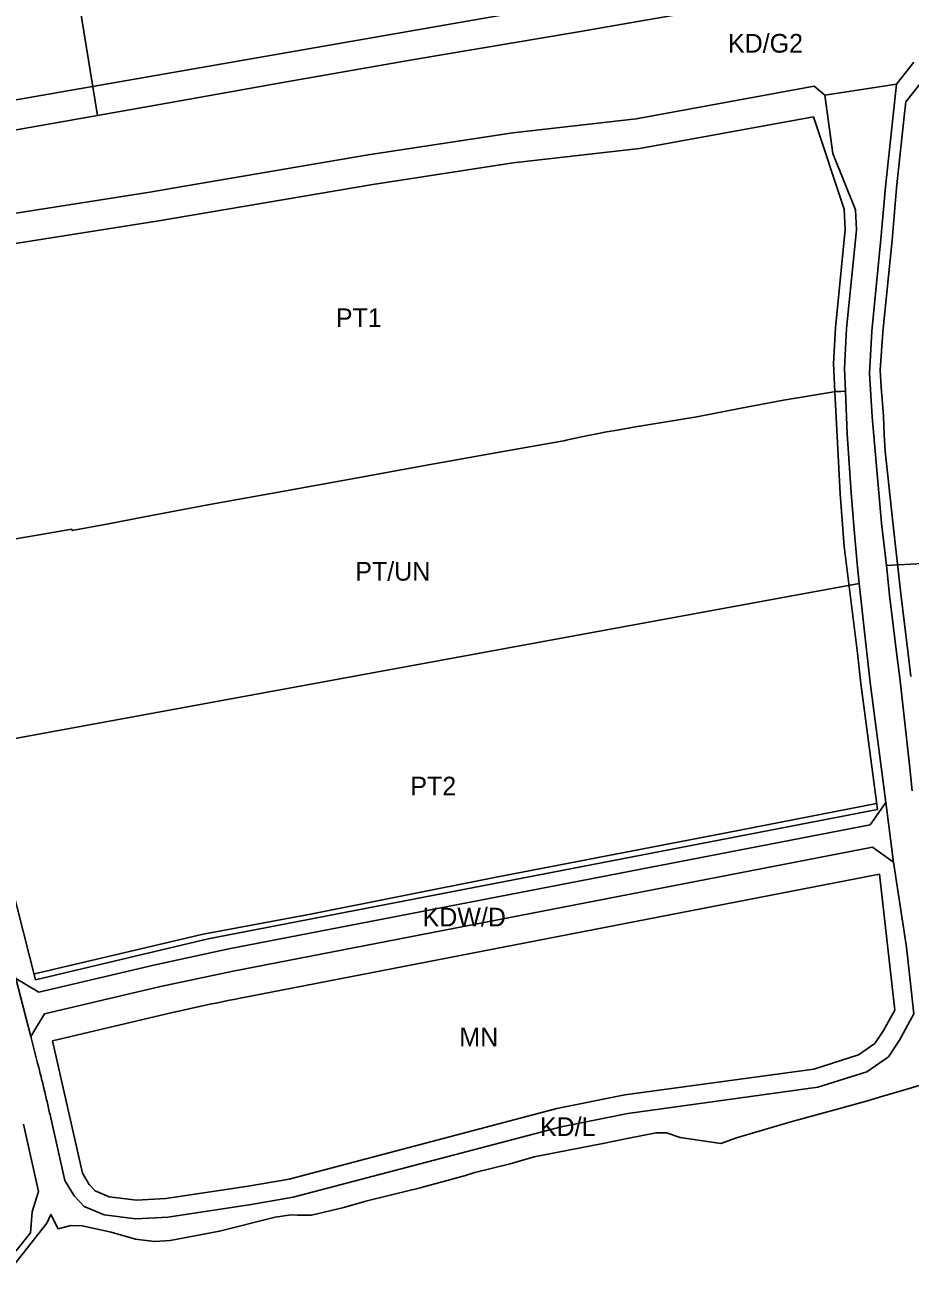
# Model space of a CAD drawing. Extents: x 7436680 to 7439366, y 5548361 to 5550775.
# Drawn here: x 7437960 to 7438434, y 5548459 to 5549127 of the extents above; entities that cross this region are included whole.
import ezdxf

# ---------------------------------------------------------------- set-up
doc = ezdxf.new("R2010")
doc.units = 0
for name, color, linetype in [('linie_rozgraniczajace', 7, 'Continuous'), ('linie_zabudowy_azurowe', 7, 'Continuous'), ('linie_zabudowy_nieprzekraczalne', 7, 'Continuous'), ('oznaczenia_przeznaczen', 7, 'Continuous')]:
    doc.layers.add(name, color=color, linetype=linetype)

msp = doc.modelspace()

# ---------------------------------------------------------------- linework, layer by layer
at = {"layer": 'linie_rozgraniczajace'}
for points in [[(7437970.79, 5549253.27), (7438227.34, 5549301.19), (7438338.8, 5549322.13), (7438378.49, 5549334.48), (7438391.14, 5549280.09), (7438396.35, 5549239.37), (7438392.82, 5549198.47), (7438390.24, 5549185.26), (7438355.6, 5549161.53), (7438356.27, 5549140.95), (7438335.28, 5549136.91), (7438255.31, 5549123.14), (7438167.47, 5549108.23), (7438100.24, 5549096.55), (7438038.34, 5549085.45), (7437999.18, 5549078.49), (7437982.05, 5549183.92)], [(7437920.81, 5548738.78), (7438406.56, 5548827.93), (7438408.3, 5548811.89), (7438409.18, 5548803.76), (7438412.31, 5548775.06), (7438420.83, 5548710.69), (7438412.33, 5548698.87), (7438069.39, 5548632.36), (7438029.98, 5548623.9), (7437967.7, 5548609.21), (7437955.49, 5548616.6), (7437930.18, 5548715.57)], [(7437955.49, 5548616.6), (7437967.7, 5548609.21), (7438029.98, 5548623.9), (7438069.39, 5548632.36), (7438412.33, 5548698.87), (7438420.83, 5548710.69), (7438421.18, 5548708.05), (7438424.26, 5548682.9), (7438424.86, 5548678.91), (7438413.54, 5548686.89), (7438071.68, 5548620.58), (7438032.74, 5548612.22), (7437970.68, 5548597.58), (7437963.42, 5548585.6)], [(7437963.42, 5548585.6), (7437970.68, 5548597.58), (7438032.74, 5548612.22), (7438071.68, 5548620.58), (7438413.54, 5548686.89), (7438424.86, 5548678.91), (7438431.81, 5548633.26), (7438435.76, 5548597.64), (7438427.97, 5548583.58), (7438422.13, 5548574.71), (7438410.62, 5548566.65), (7438384.45, 5548558.33), (7438282.82, 5548544.35), (7438247.05, 5548537.24), (7438103.69, 5548499.45), (7438081.35, 5548495.63), (7438036.67, 5548488.84), (7438019.63, 5548487.85), (7438002.69, 5548490), (7437991.89, 5548494.62), (7437986.71, 5548500.29), (7437981.61, 5548508.52), (7437974.12, 5548541.96), (7437973.92, 5548542.84), (7437973.72, 5548543.72), (7437973.52, 5548544.59), (7437973.32, 5548545.47), (7437973.13, 5548546.34), (7437972.92, 5548547.22), (7437972.72, 5548548.09), (7437972.52, 5548548.97), (7437972.32, 5548549.84), (7437972.11, 5548550.71), (7437971.91, 5548551.59), (7437971.7, 5548552.46), (7437971.5, 5548553.34), (7437971.29, 5548554.21), (7437971.08, 5548555.08), (7437970.88, 5548555.96), (7437970.67, 5548556.83), (7437970.46, 5548557.7), (7437970.24, 5548558.57), (7437970.03, 5548559.45), (7437969.82, 5548560.32), (7437969.61, 5548561.19), (7437969.39, 5548562.06), (7437969.18, 5548562.93), (7437968.96, 5548563.81), (7437968.75, 5548564.68), (7437968.53, 5548565.55), (7437968.31, 5548566.42), (7437968.09, 5548567.29), (7437967.88, 5548568.16), (7437967.66, 5548569.03), (7437967.43, 5548569.9), (7437967.21, 5548570.77), (7437967.1, 5548571.23)]]:
    msp.add_lwpolyline(points, close=True, dxfattribs=at)
for points in [[(7437982.05, 5549183.92), (7437999.18, 5549078.49), (7437856.52, 5549053.27), (7437786.66, 5549040.99), (7437679.21, 5549022.5), (7437673.72, 5549026.62), (7437664.11, 5549110.67), (7437673.64, 5549122.45), (7437672.21, 5549132.35)], [(7437471.46, 5549022.59), (7437478.39, 5549011.74), (7437481.28, 5549007.22), (7437496.12, 5549002.15), (7437548.26, 5549000.19), (7437570.44, 5549003.41), (7437657.52, 5549018.7), (7437677.73, 5549022.24), (7437679.21, 5549022.5), (7437786.66, 5549040.99), (7437856.52, 5549053.27), (7437999.18, 5549078.49), (7438038.34, 5549085.45), (7438100.24, 5549096.55), (7438167.47, 5549108.23), (7438255.31, 5549123.14), (7438335.28, 5549136.91), (7438356.27, 5549140.95), (7438358.93, 5549141.46), (7438420.86, 5549152.06), (7438591.21, 5549182.25)], [(7438435.66, 5549107.09), (7438426.37, 5549095.2), (7438388.15, 5549089.37), (7438382.5, 5549094.11), (7438287.23, 5549076.66), (7438221.26, 5549069.25), (7438143.81, 5549057.42), (7438039.46, 5549039.63), (7438027.04, 5549037.51), (7437861.01, 5549011.31), (7437832.52, 5549006.81), (7437758.08, 5548995.07), (7437731.3, 5548990.27), (7437649.47, 5548976.03), (7437591.52, 5548963.81), (7437544.99, 5548946.89), (7437509.03, 5548916.21), (7437509.07, 5548916.02), (7437435.77, 5548900.76)], [(7438453.56, 5548839.39), (7438421.02, 5548837.58), (7438418.48, 5548860.27), (7438413.5, 5548917.13), (7438411.97, 5548940.42), (7438413.17, 5548963.05), (7438418.1, 5549012.33), (7438420.51, 5549040.29), (7438426.37, 5549095.2), (7438435.66, 5549107.09)], [(7437861.01, 5549011.31), (7438027.04, 5549037.51), (7438039.46, 5549039.63), (7438143.81, 5549057.42), (7438221.26, 5549069.25), (7438287.23, 5549076.66), (7438382.5, 5549094.11), (7438388.15, 5549089.37), (7438392.37, 5549058.17), (7438404.52, 5549027.94), (7438405.03, 5549017.28), (7438399.74, 5548964.4), (7438398.61, 5548943.06), (7438399.13, 5548930.92), (7438396.72, 5548930.84), (7438394.06, 5548930.74), (7438380.06, 5548928.42), (7438366.05, 5548926.1), (7438343.32, 5548921.77), (7438320.6, 5548917.45), (7438319.59, 5548917.26), (7438318.58, 5548917.07), (7438302.18, 5548914.33), (7438285.78, 5548911.58), (7438278.08, 5548910.3), (7438270.37, 5548909.01), (7438267.99, 5548908.5), (7438258.91, 5548906.59), (7438249.83, 5548904.67), (7438249.34, 5548904.58), (7438209.99, 5548897.5), (7438172.21, 5548890.7), (7438135.28, 5548884.05), (7438116.54, 5548880.68), (7438097.8, 5548877.31), (7438058.14, 5548870.17), (7438024.28, 5548863.7), (7438004.91, 5548860), (7437985.55, 5548856.3), (7437985.42, 5548856.98), (7437966.76, 5548853.84), (7437948.11, 5548850.7)], [(7437972.11, 5548550.71), (7437972.32, 5548549.84), (7437972.52, 5548548.97), (7437972.72, 5548548.09), (7437972.92, 5548547.22), (7437973.13, 5548546.34), (7437973.32, 5548545.47), (7437973.52, 5548544.59), (7437973.72, 5548543.72), (7437973.92, 5548542.84), (7437974.12, 5548541.96), (7437981.61, 5548508.52), (7437986.71, 5548500.29), (7437991.89, 5548494.62), (7438002.69, 5548490), (7438019.63, 5548487.85), (7438036.67, 5548488.84), (7438081.35, 5548495.63), (7438103.69, 5548499.45), (7438247.05, 5548537.24), (7438282.82, 5548544.35), (7438384.45, 5548558.33), (7438410.62, 5548566.65), (7438422.13, 5548574.71), (7438427.97, 5548583.58), (7438435.76, 5548597.64), (7438431.81, 5548633.26), (7438424.86, 5548678.91), (7438424.26, 5548682.9), (7438421.18, 5548708.05), (7438420.83, 5548710.69), (7438412.31, 5548775.06), (7438409.18, 5548803.76), (7438408.3, 5548811.89), (7438406.56, 5548827.93), (7438405.61, 5548836.69), (7438403.76, 5548856.68), (7438402.23, 5548876.43), (7438400.11, 5548908.13), (7438399.13, 5548930.92), (7438398.61, 5548943.06), (7438399.74, 5548964.4), (7438405.03, 5549017.28), (7438404.52, 5549027.94), (7438392.37, 5549058.17), (7438388.15, 5549089.37), (7438426.37, 5549095.2), (7438420.51, 5549040.29), (7438418.1, 5549012.33), (7438413.17, 5548963.05), (7438411.97, 5548940.42), (7438413.5, 5548917.13), (7438418.48, 5548860.27), (7438421.02, 5548837.58), (7438422.79, 5548821.76), (7438426.69, 5548789.64), (7438428.23, 5548777.45), (7438433.39, 5548730.97), (7438434.81, 5548717.07)], [(7437948.11, 5548850.7), (7437966.76, 5548853.84), (7437985.42, 5548856.98), (7437985.55, 5548856.3), (7438004.91, 5548860), (7438024.28, 5548863.7), (7438058.14, 5548870.17), (7438097.8, 5548877.31), (7438116.54, 5548880.68), (7438135.28, 5548884.05), (7438172.21, 5548890.7), (7438209.99, 5548897.5), (7438249.34, 5548904.58), (7438249.83, 5548904.67), (7438258.91, 5548906.59), (7438267.99, 5548908.5), (7438270.37, 5548909.01), (7438278.08, 5548910.3), (7438285.78, 5548911.58), (7438302.18, 5548914.33), (7438318.58, 5548917.07), (7438319.59, 5548917.26), (7438320.6, 5548917.45), (7438343.32, 5548921.77), (7438366.05, 5548926.1), (7438380.06, 5548928.42), (7438394.06, 5548930.74), (7438396.72, 5548930.84), (7438399.13, 5548930.92), (7438400.11, 5548908.13), (7438402.23, 5548876.43), (7438403.76, 5548856.68), (7438405.61, 5548836.69), (7438406.56, 5548827.93), (7437920.81, 5548738.78)], [(7438434.81, 5548717.07), (7438433.39, 5548730.97), (7438428.23, 5548777.45), (7438426.69, 5548789.64), (7438422.79, 5548821.76), (7438421.02, 5548837.58), (7438453.56, 5548839.39)], [(7437955.49, 5548616.6), (7437963.42, 5548585.6), (7437967.1, 5548571.23), (7437967.21, 5548570.77), (7437967.43, 5548569.9), (7437967.66, 5548569.03), (7437967.88, 5548568.16), (7437968.09, 5548567.29), (7437968.31, 5548566.42), (7437968.53, 5548565.55), (7437968.75, 5548564.68), (7437968.96, 5548563.81), (7437969.18, 5548562.93), (7437969.39, 5548562.06), (7437969.61, 5548561.19), (7437969.82, 5548560.32), (7437970.03, 5548559.45), (7437970.24, 5548558.57), (7437970.46, 5548557.7), (7437970.67, 5548556.83), (7437970.88, 5548555.96), (7437971.08, 5548555.08), (7437971.29, 5548554.21), (7437971.5, 5548553.34), (7437971.7, 5548552.46), (7437971.91, 5548551.59), (7437972.11, 5548550.71)], [(7438452.9, 5548563.64), (7438433.18, 5548557.74)], [(7438433.18, 5548557.74), (7438417.3, 5548552.98), (7438410.97, 5548551.08), (7438395.5, 5548546.84), (7438369.89, 5548539.83), (7438340.86, 5548531.23), (7438332.43, 5548528.27), (7438310.72, 5548531.5), (7438303.5, 5548534.03), (7438297.9, 5548534.04), (7438283.31, 5548531.04), (7438269.41, 5548528.18), (7438232.68, 5548521.09), (7438219.82, 5548517.37), (7438200.99, 5548512.65), (7438195.85, 5548511.14), (7438171.6, 5548504.5), (7438156.44, 5548500.73), (7438142.57, 5548497.47), (7438130.8, 5548493.94), (7438113.55, 5548489.84), (7438106.04, 5548489.93), (7438102.64, 5548490.04), (7438094.18, 5548488.75), (7438064.36, 5548481.29), (7438038.04, 5548476.36), (7438029.56, 5548475.82), (7438019.5, 5548477.01), (7438006.34, 5548480.78), (7437990.99, 5548484.26), (7437984.78, 5548484.31), (7437978.05, 5548482.59), (7437974.08, 5548490.33), (7437971.92, 5548485.54), (7437950.99, 5548458.92)], [(7437959.48, 5548538.68), (7437967.57, 5548502.61), (7437964.13, 5548491.63), (7437963.3, 5548480.5), (7437955.39, 5548470.58)], [(7437955.39, 5548470.58), (7437963.3, 5548480.5), (7437964.13, 5548491.63), (7437967.57, 5548502.61), (7437959.48, 5548538.68)]]:
    msp.add_lwpolyline(points, dxfattribs=at)
at = {"layer": 'linie_zabudowy_azurowe'}
msp.add_lwpolyline([(7437965.37, 5548619.01), (7438055.69, 5548640.24), (7438113.08, 5548650.96), (7438211.44, 5548670.66), (7438335.34, 5548694.52), (7438415.84, 5548710.23)], dxfattribs=at)
at = {"layer": 'linie_zabudowy_nieprzekraczalne'}
for points in [[(7437672.18, 5549037.52), (7438316.41, 5549149.98)], [(7438442.26, 5549099.57), (7438431.39, 5549085.71)], [(7438431.39, 5549085.71), (7438430.55, 5549077.88)], [(7438382.01, 5549077.76), (7438290.11, 5549060.93)], [(7438398.5, 5549028.26), (7438382.01, 5549077.76)], [(7438430.55, 5549077.88), (7438426.49, 5549039.78)], [(7438289.01, 5549060.77), (7438223.05, 5549053.35)], [(7438290.11, 5549060.93), (7438289.01, 5549060.77)], [(7438223.67, 5549053.43), (7438146.36, 5549041.62)], [(7438223.05, 5549053.35), (7438223.67, 5549053.43)], [(7438146.36, 5549041.62), (7438029.73, 5549021.74)], [(7438426.48, 5549039.66), (7438424.07, 5549011.78)], [(7438426.49, 5549039.78), (7438426.48, 5549039.72)], [(7438426.48, 5549039.72), (7438426.48, 5549039.66)], [(7438399.01, 5549017.44), (7438398.5, 5549028.26)], [(7438029.53, 5549021.7), (7437869.25, 5548996.41)], [(7438029.73, 5549021.74), (7438029.53, 5549021.7)], [(7438393.76, 5548964.85), (7438399.01, 5549017.44)], [(7438424.07, 5549011.78), (7438419.17, 5548962.74)], [(7438392.74, 5548945.7), (7438393.76, 5548964.85)], [(7438419.16, 5548962.6), (7438419.15, 5548962.46)], [(7438419.17, 5548962.74), (7438419.16, 5548962.6)], [(7438419.15, 5548962.46), (7438417.7, 5548942.19)], [(7438393.38, 5548930.59), (7438392.74, 5548945.7)], [(7438417.7, 5548942.19), (7438418.23, 5548933.08)], [(7438396.24, 5548876.03), (7438393.38, 5548930.59)], [(7438418.23, 5548933.08), (7438419.48, 5548917.65)], [(7438419.48, 5548917.65), (7438419.48, 5548917.59)], [(7438419.48, 5548917.59), (7438419.49, 5548917.52)], [(7438419.49, 5548917.52), (7438419.92, 5548907.64)], [(7438419.92, 5548907.64), (7438420.33, 5548898.88)], [(7438420.33, 5548898.88), (7438424.45, 5548860.86)], [(7438398.51, 5548847.87), (7438396.24, 5548876.03)], [(7438424.45, 5548860.86), (7438428.75, 5548822.48)], [(7438405.57, 5548790.78), (7438398.51, 5548847.87)], [(7438428.75, 5548822.48), (7438428.75, 5548822.45)], [(7438428.75, 5548822.45), (7438428.76, 5548822.43)], [(7438428.76, 5548822.43), (7438432.65, 5548790.39)], [(7438407.35, 5548774.46), (7438405.57, 5548790.78)], [(7438432.65, 5548790.39), (7438432.65, 5548790.38)], [(7438432.65, 5548790.38), (7438432.65, 5548790.37)], [(7438432.65, 5548790.37), (7438434.18, 5548778.15)], [(7438416.28, 5548707.01), (7438407.35, 5548774.46)], [(7437939.7, 5548718.69), (7437966, 5548615.86)], [(7438058.24, 5548637.84), (7438416.28, 5548707.01)], [(7438417.42, 5548672.36), (7438074.54, 5548605.86)], [(7438425.47, 5548599.7), (7438417.42, 5548672.36)], [(7437966, 5548615.86), (7438058.24, 5548637.84)], [(7438036.18, 5548597.62), (7437975.12, 5548583.22)], [(7438419.41, 5548588.76), (7438425.47, 5548599.7)], [(7438414.83, 5548581.81), (7438419.41, 5548588.76)], [(7437975.12, 5548583.22), (7437991, 5548512.35)], [(7438406.13, 5548575.72), (7438414.83, 5548581.81)], [(7438382.24, 5548568.12), (7438406.13, 5548575.72)], [(7438281.17, 5548554.22), (7438382.24, 5548568.12)], [(7438244.8, 5548546.99), (7438281.17, 5548554.22)], [(7438101.57, 5548509.23), (7438244.8, 5548546.99)], [(7437991, 5548512.35), (7437994.72, 5548506.35)], [(7438079.76, 5548505.5), (7438101.57, 5548509.23)], [(7437994.72, 5548506.35), (7437997.82, 5548502.96)], [(7437997.82, 5548502.96), (7438005.34, 5548499.74)], [(7438035.63, 5548498.8), (7438079.76, 5548505.5)], [(7438005.34, 5548499.74), (7438019.97, 5548497.88)], [(7438019.97, 5548497.88), (7438035.63, 5548498.8)]]:
    msp.add_lwpolyline(points, dxfattribs=at)
msp.add_arc((7438263.47, 5547632.9), 991.14, 100.98919, 103.25744, dxfattribs=at)

# ---------------------------------------------------------------- texts
at = {"layer": 'oznaczenia_przeznaczen'}
for s, p in [('KD/G2', (7438336.32, 5549112.13)), ('PT1', (7438126.59, 5548965.22)), ('PT/UN', (7438136.99, 5548829.52)), ('PT2', (7438166.42, 5548714.56)), ('KDW/D', (7438172.96, 5548644.44)), ('MN', (7438192.65, 5548580.28)), ('KD/L', (7438235.73, 5548532.3))]:
    msp.add_text(s, height=10, dxfattribs=at).set_placement(p)

doc.saveas('drawing.dxf')
